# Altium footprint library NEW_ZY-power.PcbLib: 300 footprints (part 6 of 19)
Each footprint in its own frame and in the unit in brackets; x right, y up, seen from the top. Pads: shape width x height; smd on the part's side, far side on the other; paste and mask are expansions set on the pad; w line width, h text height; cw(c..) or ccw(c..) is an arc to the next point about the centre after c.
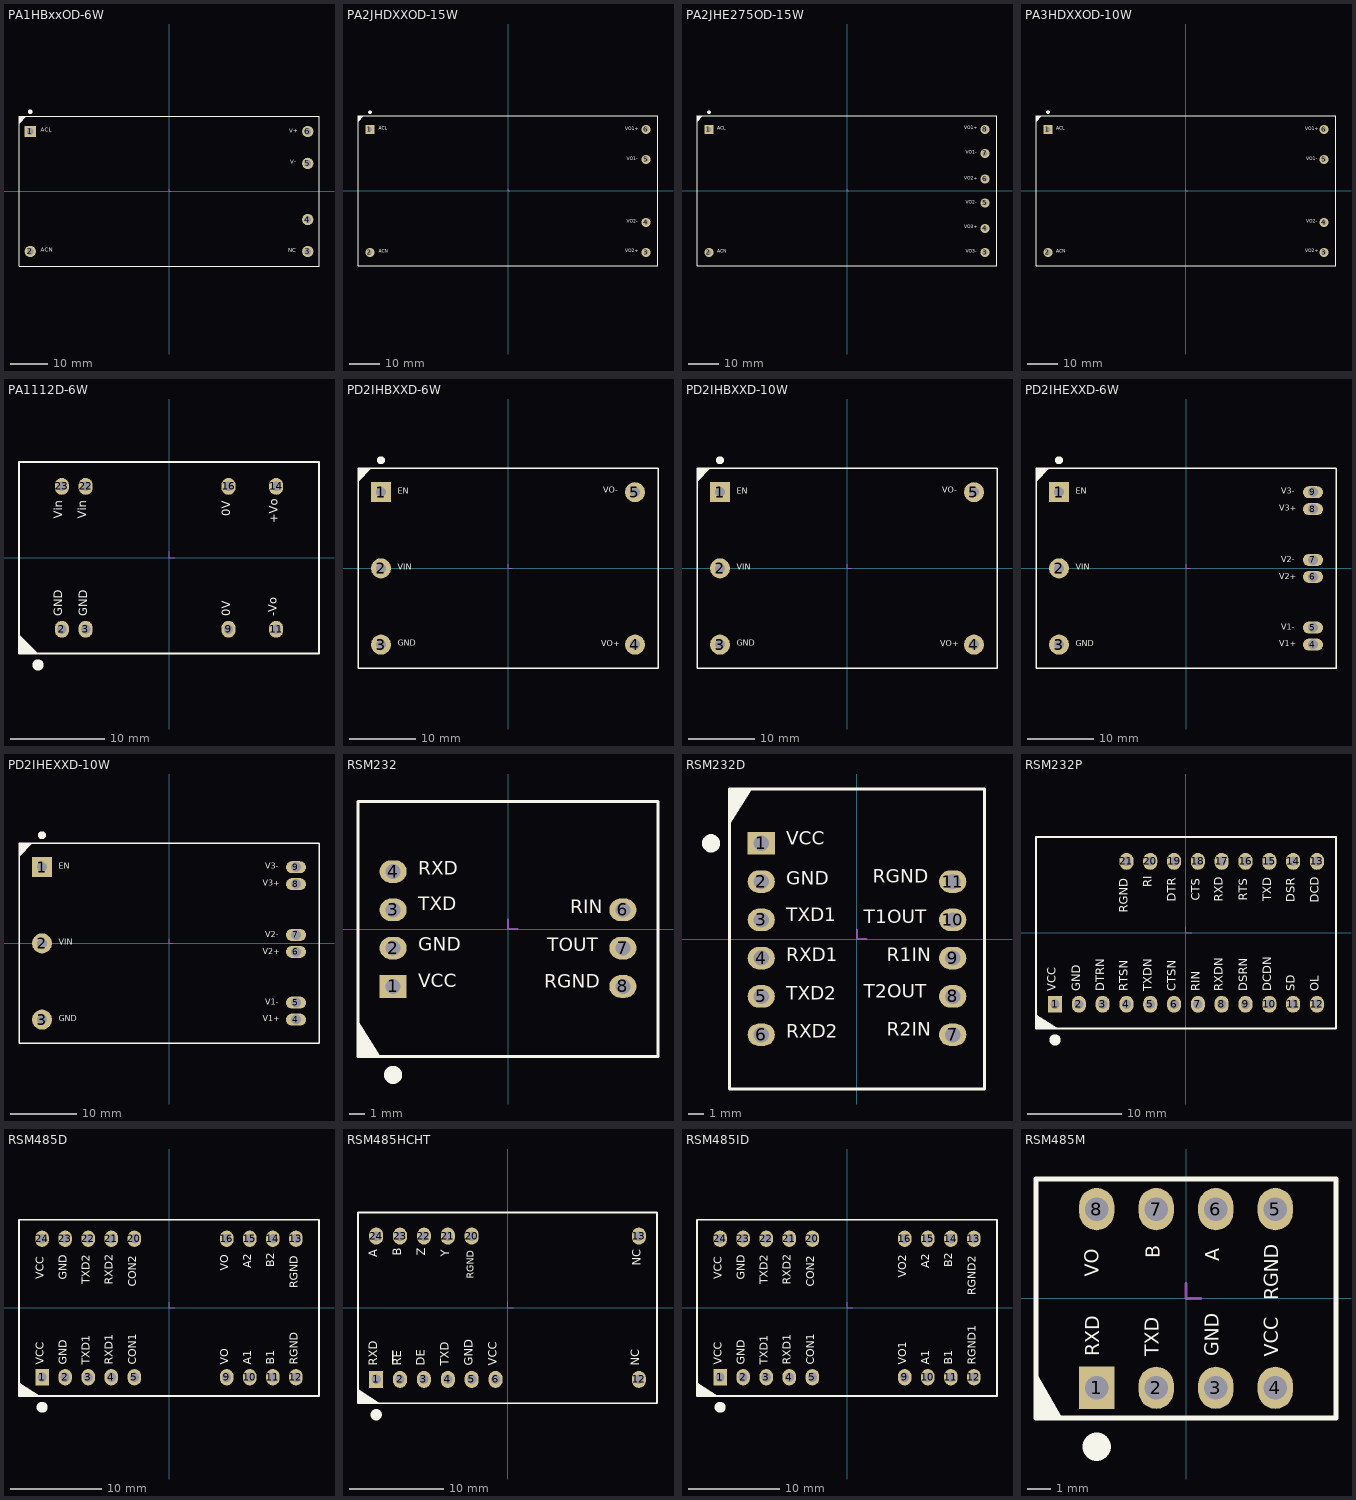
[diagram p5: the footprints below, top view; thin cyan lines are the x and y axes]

## PA1HBxxOD-6W [mm]
pads (6):
  rect 3x3 hole 1.8: 1(-37,16)
  round 3 hole 1.8: 2(-37,-16) 3(37,-16) 4(37,-7.5) 5(37,7.5) 6(37,16)
Top Overlay:
  circle w1: c-37,21.225 r0.1
  region: -40,20 -40,18.025 -38.025,20
  lines w0.2: -40,-20 40,-20 40,20 -40,20 -40,-20
  text "ACL" at -34.206,15.494 h1.78
  text "ACN" at -34.206,-16.506 h1.78
  text "V+" at 32.01,15.24 h1.78
  text "V-" at 32.371,6.987 h1.78
  text "NC" at 31.791,-16.635 h1.78
Mechanical 15:
  lines w0.127: 0,0.635 0,0 0.635,0

## PA2JHDXXOD-15W [mm]
pads (6):
  rect 3x3 hole 1.5: 1(-46,20.5)
  round 3 hole 1.5: 2(-46,-20.5) 3(46,-20.5) 4(46,-10.5) 5(46,10.5) 6(46,20.5)
Top Overlay:
  circle w1: c-46,26.225 r0.1
  region: -50,25 -50,23.025 -48.025,25
  lines w0.2: -50,-25 50,-25 50,25 -50,25 -50,-25
  text "ACL" at -43.079,19.939 h1.78
  text "ACN" at -43.079,-21.061 h1.78
  text "VO2+" at 39.142,-20.955 h1.78
  text "VO2-" at 39.503,-11.049 h1.78
  text "VO1-" at 39.503,9.779 h1.78
  text "VO1+" at 39.142,19.779 h1.78
Mechanical 15:
  lines w0.127: 0,0.635 0,0 0.635,0

## PA2JHE275OD-15W [mm]
pads (8):
  rect 3x3 hole 1.8: 1(-46,20.5)
  round 3 hole 1.8: 2(-46,-20.5) 3(46,-20.5) 4(46,-12.5) 5(46,-4) 6(46,4) 7(46,12.5) 8(46,20.5)
Top Overlay:
  circle w1: c-46,26.225 r0.1
  region: -50,25 -50,23.025 -48.025,25
  lines w0.2: -50,-25 -50,25 50,25 50,-25 -50,-25
  text "VO2-" at 39.503,-4.699 h1.78
  text "VO2+" at 39.142,3.302 h1.78
  text "VO1+" at 39.142,20.033 h1.78
  text "VO1-" at 39.503,11.938 h1.78
  text "VO3-" at 39.503,-21.082 h1.78
  text "VO3+" at 39.142,-12.954 h1.78
  text "ACN" at -43.333,-21.061 h1.78
  text "ACL" at -43.333,19.939 h1.78
Mechanical 15:
  lines w0.127: 0,0.635 0,0 0.635,0

## PA3HDXXOD-10W [mm]
pads (6):
  rect 3x3 hole 1.8: 1(-46,20.5)
  round 3 hole 1.8: 2(-46,-20.5) 3(46,-20.5) 4(46,-10.5) 5(46,10.5) 6(46,20.5)
Top Overlay:
  circle w1: c-46,26.225 r0.1
  region: -50,25 -50,23.025 -48.025,25
  lines w0.2: -50,-25 -50,25 50,25 50,-25 -50,-25
  text "VO1+" at 39.777,19.779 h1.78
  text "VO1-" at 40.086,9.779 h1.78
  text "VO2-" at 40.086,-11.049 h1.78
  text "VO2+" at 39.777,-20.955 h1.78
  text "ACN" at -43.206,-21.061 h1.78
  text "ACL" at -43.206,19.939 h1.78
Mechanical 15:
  lines w0.127: 0,0.635 0,0 0.635,0

## PA1112D-6W [mm]
height 10.3
pads (8):
  oval 1.5x1.8 hole 1: 2(-11.43,-7.62) 3(-8.89,-7.62) 9(6.35,-7.62) 11(11.43,-7.62) 14(11.43,7.62) 16(6.35,7.62) 22(-8.89,7.62) 23(-11.43,7.62)
Top Overlay:
  circle w1: c-13.97,-11.425 r0.1
  region: -16,-10.2 -14.025,-10.2 -16,-8.225
  lines w0.2: -16,-10.2 16,-10.2 16,10.2 -16,10.2 -16,-10.2
  text "0V" at 6.833,-6.223 h1.52
  text "0V" at 6.858,4.423 h1.52
  text "+Vo" at 11.938,3.683 h1.52
  text "-Vo" at 11.811,-6.223 h1.52
  text "Vin" at -8.509,4.151 h1.52
  text "Vin" at -11.049,4.151 h1.52
  text "GND" at -8.382,-6.223 h1.52
  text "GND" at -11.049,-6.223 h1.52
Mechanical 15:
  lines w0.127: 0,0.635 0,0 0.635,0

## PD2IHBXXD-6W [mm]
pads (5):
  rect 3x3 hole 1.5: 1(-19.05,11.43)
  round 3 hole 1.5: 2(-19.05,0) 3(-19.05,-11.43) 4(19.05,-11.43) 5(19.05,11.43)
Top Overlay:
  circle w1: c-19.05,16.225 r0.1
  region: -22.5,15 -22.5,13.025 -20.525,15
  lines w0.2: -22.5,-15 22.5,-15 22.5,15 -22.5,15 -22.5,-15
  text "VO-" at 14.279,11.049 h1.52
  text "VO+" at 13.97,-11.938 h1.52
  text "GND" at -16.511,-11.936 h1.52
  text "VIN" at -16.51,-0.506 h1.52
  text "EN" at -16.511,10.924 h1.52
Mechanical 15:
  lines w0.127: 0,0.635 0,0 0.635,0

## PD2IHBXXD-10W [mm]
pads (5):
  rect 3x3 hole 1.5: 1(-19.05,11.43)
  round 3 hole 1.5: 2(-19.05,0) 3(-19.05,-11.43) 4(19.05,-11.43) 5(19.05,11.43)
Top Overlay:
  circle w1: c-19.05,16.225 r0.1
  region: -22.5,15 -22.5,13.025 -20.525,15
  lines w0.2: -22.5,-15 -22.5,15 22.5,15 22.5,-15 -22.5,-15
  text "EN" at -16.511,10.924 h1.52
  text "VIN" at -16.51,-0.506 h1.52
  text "GND" at -16.511,-11.936 h1.52
  text "VO+" at 13.97,-11.938 h1.52
  text "VO-" at 14.279,11.049 h1.52
Mechanical 15:
  lines w0.127: 0,0.635 0,0 0.635,0

## PD2IHEXXD-6W [mm]
pads (9):
  rect 3x3 hole 1.5 unplated: 1(-19.05,11.43)
  round 3 hole 1.5 unplated: 2(-19.05,0) 3(-19.05,-11.43)
  oval 3x1.8 hole 1.5 unplated: 4(19.05,-11.43) 5(19.05,-8.89) 6(19.05,-1.27) 7(19.05,1.27) 8(19.05,8.89) 9(19.05,11.43)
Top Overlay:
  circle w1: c-19.05,16.225 r0.1
  region: -22.5,15 -22.5,13.025 -20.525,15
  lines w0.2: -22.5,-15 22.5,-15 22.5,15 -22.5,15 -22.5,-15
  text "EN" at -16.511,10.922 h1.52
  text "VIN" at -16.51,-0.508 h1.52
  text "GND" at -16.511,-11.938 h1.52
  text "V1+" at 13.97,-11.938 h1.52
  text "V1-" at 14.279,-9.525 h1.52
  text "V2+" at 13.97,-1.905 h1.52
  text "V2-" at 14.279,0.635 h1.52
  text "V3+" at 13.97,8.382 h1.52
  text "V3-" at 14.279,10.922 h1.52
Mechanical 15:
  lines w0.127: 0,0.635 0,0 0.635,0

## PD2IHEXXD-10W [mm]
pads (9):
  rect 3x3 hole 1.5 unplated: 1(-19.05,11.43)
  round 3 hole 1.5 unplated: 2(-19.05,0) 3(-19.05,-11.43)
  oval 3x1.8 hole 1.5 unplated: 4(19.05,-11.43) 5(19.05,-8.89) 6(19.05,-1.27) 7(19.05,1.27) 8(19.05,8.89) 9(19.05,11.43)
Top Overlay:
  circle w1: c-19.05,16.225 r0.1
  region: -22.5,15 -22.5,13.025 -20.525,15
  lines w0.2: -22.5,-15 -22.5,15 22.5,15 22.5,-15 -22.5,-15
  text "V3-" at 14.406,10.922 h1.52
  text "V3+" at 14.097,8.382 h1.52
  text "V2-" at 14.406,0.635 h1.52
  text "V2+" at 14.097,-1.905 h1.52
  text "V1-" at 14.406,-9.525 h1.52
  text "V1+" at 14.097,-11.938 h1.52
  text "GND" at -16.511,-11.938 h1.52
  text "VIN" at -16.51,-0.508 h1.52
  text "EN" at -16.511,10.922 h1.52
Mechanical 15:
  lines w0.127: 0,0.635 0,0 0.635,0

## RSM232 [mm]
height 7.1
pads (7):
  rect 1.8x1.5 hole 1: 1(-7.62,-3.81)
  oval 1.8x1.5 hole 1: 2(-7.62,-1.27) 3(-7.62,1.27) 4(-7.62,3.81) 6(7.62,1.27) 7(7.62,-1.27) 8(7.62,-3.81)
Top Overlay:
  circle w1: c-7.62,-9.675 r0.1
  region: -9.95,-6.12 -9.95,-8.45 -8.49,-8.45
  lines w0.2: -9.95,-8.45 -9.95,8.45 9.95,8.45 9.95,-8.45 -9.95,-8.45
  text "RGND" at 2.413,-4.191 h1.52
  text "RXD" at -5.969,3.302 h1.52
  text "TXD" at -5.969,0.94 h1.52
  text "GND" at -5.969,-1.753 h1.52
  text "VCC" at -5.969,-4.166 h1.52
  text "TOUT" at 2.597,-1.778 h1.52
  text "RIN" at 4.116,0.762 h1.52
Mechanical 15:
  lines w0.127: 0,0.635 0,0 0.635,0

## RSM232D [mm]
height 7.1
pads (11):
  rect 1.8x1.5 hole 1: 1(-6.35,6.35)
  oval 1.8x1.5 hole 1: 2(-6.35,3.81) 3(-6.35,1.27) 4(-6.35,-1.27) 5(-6.35,-3.81) 6(-6.35,-6.35) 7(6.35,-6.35) 8(6.35,-3.81) 9(6.35,-1.27) 10(6.35,1.27) 11(6.35,3.81)
Top Overlay:
  circle w1: c-9.675,6.35 r0.1
  region: -8.45,7.62 -8.45,9.95 -6.99,9.95
  lines w0.2: -8.45,-9.95 8.45,-9.95 8.45,9.95 -8.45,9.95 -8.45,-9.95
  text "RXD2" at -4.7,-6.858 h1.52
  text "TXD2" at -4.7,-4.318 h1.52
  text "R2IN" at 1.977,-6.731 h1.52
  text "T2OUT" at 0.458,-4.191 h1.52
  text "R1IN" at 1.977,-1.778 h1.52
  text "RXD1" at -4.7,-1.778 h1.52
  text "TXD1" at -4.7,0.889 h1.52
  text "GND" at -4.7,3.302 h1.52
  text "VCC" at -4.699,5.969 h1.52
  text "T1OUT" at 0.458,0.762 h1.52
  text "RGND" at 1.032,3.429 h1.52
Mechanical 15:
  lines w0.127: 0,0.635 0,0 0.635,0

## RSM232P [mm]
height 10.5
pads (21):
  rect 1.5x1.8 hole 1: 1(-13.97,-7.62)
  oval 1.5x1.8 hole 1: 2(-11.43,-7.62) 3(-8.89,-7.62) 4(-6.35,-7.62) 5(-3.81,-7.62) 6(-1.27,-7.62) 7(1.27,-7.62) 8(3.81,-7.62) 9(6.35,-7.62) 10(8.89,-7.62) 11(11.43,-7.62) 12(13.97,-7.62) 13(13.97,7.62) 14(11.43,7.62) 15(8.89,7.62) 16(6.35,7.62) 17(3.81,7.62) 18(1.27,7.62) 19(-1.27,7.62) 20(-3.81,7.62) 21(-6.35,7.62)
Top Overlay:
  circle w1: c-13.97,-11.425 r0.1
  region: -13.67,-10.2 -16,-10.2 -16,-8.74
  lines w0.2: -16,-10.2 16,-10.2 16,10.2 -16,10.2 -16,-10.2
  text "VCC" at -13.564,-6.223 h1.52
  text "GND" at -10.947,-6.224 h1.52
  text "DTRN" at -8.407,-6.224 h1.52
  text "RTSN" at -5.893,-6.224 h1.52
  text "TXDN" at -3.353,-6.224 h1.52
  text "CTSN" at -0.787,-6.224 h1.52
  text "RIN" at 1.762,-6.224 h1.52
  text "RXDN" at 4.267,-6.224 h1.52
  text "DSRN" at 6.833,-6.224 h1.52
  text "DCDN" at 9.398,-6.224 h1.52
  text "SD" at 11.938,-6.224 h1.52
  text "OL" at 14.478,-6.224 h1.52
  text "DCD" at 14.478,3.217 h1.52
  text "DSR" at 11.938,3.236 h1.52
  text "TXD" at 9.414,3.37 h1.52
  text "RTS" at 6.833,3.443 h1.52
  text "RXD" at 4.267,3.293 h1.52
  text "CTS" at 1.778,3.404 h1.52
  text "DTR" at -0.787,3.314 h1.52
  text "RI" at -3.353,4.856 h1.52
  text "RGND" at -5.893,2.159 h1.52
Mechanical 15:
  lines w0.127: 0,0.635 0,0 0.635,0

## RSM485D [mm]
height 9.144
pads (18):
  rect 1.5x1.8 hole 1: 1(-13.97,-7.62)
  oval 1.5x1.8 hole 1: 2(-11.43,-7.62) 3(-8.89,-7.62) 4(-6.35,-7.62) 5(-3.81,-7.62) 9(6.35,-7.62) 10(8.89,-7.62) 11(11.43,-7.62) 12(13.97,-7.62) 13(13.97,7.62) 14(11.43,7.62) 15(8.89,7.62) 16(6.35,7.62) 20(-3.81,7.62) 21(-6.35,7.62) 22(-8.89,7.62) 23(-11.43,7.62) 24(-13.97,7.62)
Top Overlay:
  circle w1: c-13.97,-10.928 r0.1
  region: -14.18,-9.703 -16.51,-9.703 -16.51,-8.243
  lines w0.2: -16.51,-9.703 -16.51,9.703 16.51,9.703 16.51,-9.703 -16.51,-9.703
  text "VO" at 6.858,4.088 h1.52
  text "VO" at 6.858,-6.223 h1.52
  text "RGND" at 14.478,-6.224 h1.52
  text "A1" at 9.398,-6.224 h1.52
  text "B1" at 11.938,-6.224 h1.52
  text "RGND" at 14.478,2.159 h1.52
  text "A2" at 9.398,4.392 h1.52
  text "B2" at 11.938,4.493 h1.52
  text "TXD2" at -8.382,2.611 h1.52
  text "RXD2" at -5.842,2.533 h1.52
  text "GND" at -10.922,3.108 h1.52
  text "CON2" at -3.302,2.345 h1.52
  text "VCC" at -13.462,3.172 h1.52
  text "VCC" at -13.462,-6.223 h1.52
  text "CON1" at -3.302,-6.224 h1.52
  text "GND" at -10.922,-6.224 h1.52
  text "RXD1" at -5.842,-6.224 h1.52
  text "TXD1" at -8.382,-6.224 h1.52
Mechanical 15:
  lines w0.127: 0,0.635 0,0 0.635,0

## RSM485HCHT [mm]
height 6.5
pads (13):
  rect 1.5x1.8 hole 1: 1(-13.97,-7.62)
  oval 1.5x1.8 hole 1: 2(-11.43,-7.62) 3(-8.89,-7.62) 4(-6.35,-7.62) 5(-3.81,-7.62) 6(-1.27,-7.62) 12(13.97,-7.62) 13(13.97,7.62) 20(-3.81,7.62) 21(-6.35,7.62) 22(-8.89,7.62) 23(-11.43,7.62) 24(-13.97,7.62)
Top Overlay:
  circle w1: c-13.97,-11.375 r0.1
  region: -13.57,-10.15 -15.9,-10.15 -15.9,-8.69
  lines w0.152: -12.22,-6.02 -12.22,-4.589
  lines w0.2: -15.9,-10.15 -15.9,10.15 15.9,10.15 15.9,-10.15 -15.9,-10.15
  text "VCC" at -0.852,-6.147 h1.52
  text "Y" at -5.879,5.4 h1.52
  text "RGND" at -3.334,3.097 h1.27
  text "Z" at -8.424,5.522 h1.52
  text "B" at -10.968,5.556 h1.52
  text "A" at -13.513,5.382 h1.52
  text "NC" at 14.478,4.483 h1.52
  text "GND" at -3.389,-6.147 h1.52
  text "TXD" at -5.927,-6.147 h1.52
  text "DE" at -8.464,-6.147 h1.52
  text "RE" at -11.001,-6.147 h1.52
  text "RXD" at -13.538,-6.147 h1.52
  text "NC" at 14.351,-6.147 h1.52
Mechanical 15:
  lines w0.127: 0,0.635 0,0 0.635,0

## RSM485ID [mm]
height 9.144
pads (18):
  rect 1.5x1.8 hole 1: 1(-13.97,-7.62)
  oval 1.5x1.8 hole 1: 2(-11.43,-7.62) 3(-8.89,-7.62) 4(-6.35,-7.62) 5(-3.81,-7.62) 9(6.35,-7.62) 10(8.89,-7.62) 11(11.43,-7.62) 12(13.97,-7.62) 13(13.97,7.62) 14(11.43,7.62) 15(8.89,7.62) 16(6.35,7.62) 20(-3.81,7.62) 21(-6.35,7.62) 22(-8.89,7.62) 23(-11.43,7.62) 24(-13.97,7.62)
Top Overlay:
  circle w1: c-13.97,-10.928 r0.1
  region: -14.18,-9.703 -16.51,-9.703 -16.51,-8.243
  lines w0.2: -16.51,-9.703 16.51,-9.703 16.51,9.703 -16.51,9.703 -16.51,-9.703
  text "TXD1" at -8.382,-6.224 h1.52
  text "RXD1" at -5.842,-6.224 h1.52
  text "GND" at -10.922,-6.224 h1.52
  text "CON1" at -3.302,-6.224 h1.52
  text "VCC" at -13.462,-6.223 h1.52
  text "VCC" at -13.462,3.17 h1.52
  text "CON2" at -3.302,2.342 h1.52
  text "GND" at -10.922,3.106 h1.52
  text "RXD2" at -5.842,2.531 h1.52
  text "TXD2" at -8.382,2.608 h1.52
  text "B2" at 11.938,4.491 h1.52
  text "A2" at 9.398,4.39 h1.52
  text "RGND2" at 14.478,1.397 h1.52
  text "B1" at 11.938,-6.224 h1.52
  text "A1" at 9.398,-6.224 h1.52
  text "RGND1" at 14.478,-6.224 h1.52
  text "VO1" at 6.858,-6.223 h1.52
  text "VO2" at 6.858,3.338 h1.52
Mechanical 15:
  lines w0.127: 0,0.635 0,0 0.635,0

## RSM485M [mm]
height 7.7
pads (8):
  rect 1.5x1.8 hole 1: 1(-3.81,-3.81)
  oval 1.5x1.8 hole 1: 2(-1.27,-3.81) 3(1.27,-3.81) 4(3.81,-3.81) 5(3.81,3.81) 6(1.27,3.81) 7(-1.27,3.81) 8(-3.81,3.81)
Top Overlay:
  circle w1: c-3.81,-6.325 r0.1
  region: -5.284,-5.1 -6.4,-3.161 -6.4,-5.1
  lines w0.2: -6.4,-5.1 6.4,-5.1 6.4,5.1 -6.4,5.1 -6.4,-5.1
  text "RXD" at -3.491,-2.459 h1.02
  text "TXD" at -0.94,-2.459 h1.02
  text "GND" at 1.6,-2.459 h1.02
  text "VCC" at 4.14,-2.485 h1.02
  text "VO" at -3.505,0.935 h1.02
  text "B" at -0.914,1.711 h1.02
  text "A" at 1.64,1.595 h1.02
  text "RGND" at 4.14,-0.072 h1.02
Mechanical 15:
  lines w0.127: 0,0.635 0,0 0.635,0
